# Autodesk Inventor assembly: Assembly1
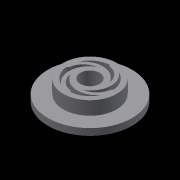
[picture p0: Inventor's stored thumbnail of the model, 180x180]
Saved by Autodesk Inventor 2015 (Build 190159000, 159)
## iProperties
Created: 2015-09
Part Number: Assembly1
Document SubType Name: Assembly
Designer: Drano
Author: Drano
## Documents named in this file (3)
- C:\Users\Drano\Documents\Xtrail Radiator bushes\Assembly1.iam
- C:\Users\Drano\Documents\Xtrail Radiator bushes\Part2.ipt
- C:\Users\Drano\Documents\Xtrail Radiator bushes\Part1.ipt
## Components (2 placed, 2 different names)
1. Part2:1 — Mate:1, Mate:2, Mate:3
2. Part1:1 — Mate:1, Mate:2, Mate:3
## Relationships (3: Mate 3)
- Mate:1: Part2:1 ↔ Part1:1
- Mate:2: Part2:1 ↔ Part1:1
- Mate:3: Part2:1 ↔ Part1:1
